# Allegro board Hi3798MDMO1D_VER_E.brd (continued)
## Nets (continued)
GND: C1.2 C2.2 C3.2 C4.2 C5.2 C7.2 C8.2 C9.2 C10.2 C11.2 C12.2 C13.2 C14.2 C15.2 C16.2 C17.2 C18.2 C19.2 C20.2 C21.2 C22.1 C23.2 C24.2 C25.2 C26.2 C27.2 C28.2 C29.2 C30.2 C31.2 C33.1 C34.2 C35.2 C36.2 C37.2 C38.2 C39.2 C40.2 C41.2 C42.1 C43.2 C44.2 C45.2 C46.2 C47.2 C48.2 C49.2 C50.2 C51.2 C52.2 C53.2 C56.2 C57.2 C58.2 C59.2 C60.2 C61.2 C62.2 C63.2 C64.2 C66.2 C67.2 C68.2 C69.2 C70.2 C71.2 C72.2 C74.2 C75.2 C78.2 C79.2 C85.2 C86.2 C87.2 C88.2 C89.2 C90.2 C91.2 C92.2 C93.2 C94.2 C95.2 C96.2 C97.2 C98.2 C99.2 C100.2 C101.2 C102.2 C103.2 C104.2 C105.2 C106.2 C107.2 C108.2 C109.2 C110.2 C111.2 C112.2 C113.2 C114.2 C115.2 C116.2 C117.2 C118.2 C119.2 C120.2 C121.2 C123.2 C124.2 C126.2 C127.2 C128.2 C129.2 C130.2 C131.2 C132.2 C133.2 C134.2 C135.2 C137.2 C138.2 C139.2 C140.2 C142.2 C143.2 C144.2 C149.2 C150.2 C151.2 C152.2 C153.2 C154.2 C158.2 C161.2 C162.2 C164.2 C167.2 C168.2 C169.2 C177.2 C180.2 C181.2 C182.2 C184.2 C185.2 C186.2 C188.2 C189.2 C190.2 C191.2 C193.2 C194.2 C195.2 C196.2 C197.2 C198.2 C199.2 C200.2 C201.2 C203.2 C204.2 C205.2 C208.2 C209.2 C211.2 C212.2 C213.2 C216.2 C218.2 C219.2 C220.2 C221.2 C225.2 C226.2 C227.2 C228.2 C232.2 C235.2 C236.2 C237.2 C238.2 C241.2 C243.2 C245.2 C248.2 C249.2 C250.1 C251.2 C255.1 C257.2 C263.2 C264.2 C270.2 C271.2 C275.2 C278.2 C279.2 C281.2 C282.2 C283.2 C284.2 C285.2 C286.2 C287.2 C288.2 C289.2 C290.2 C291.2 C292.2 C293.2 C295.2 C297.2 C298.2 C299.2 C300.2 C301.2 C302.2 C303.2 C304.2 C305.2 C306.2 C307.2 C316.2 C317.2 C320.2 C323.2 C324.2 C334.2 C336.2 C339.2 C363.2 C364.2 C365.2 C391.2 D1.2 D3.2 D6.2 D9.1 J1.2 J1.3 J2.2 J2.7 J2.9 J2.10 J2.12 J3.1 J4.2 J4.3 J5.2 J5.3 J10.2 J10.3 J12.4 J12.5 J12.6 J13.4 J13.7 J13.10 J13.11 J18.1 J21.6 J21.10 J21.11 J21.12 J21.13 J21.14 J21.15 J26.2 J26.5 J26.8 J26.11 J26.17 J26.20 J26.21 J26.22 J26.23 J34.5 LED1.2 Q1.2 Q2.2 Q4.2 Q5.2 Q8.2 R8.1 R9.2 R11.1 R13.1 R18.1 R25.1 R32.1 R38.1 R39.2 R41.1 R42.1 R43.2 R45.2 R48.2 R50.2 R51.2 R52.2 R54.1 R55.1 R56.1 R57.2 R61.1 R71.1 R75.1 R78.1 R82.2 R85.2 R87.1 R89.2 R93.2 R99.1 R100.2 R103.2 R104.2 R124.2 R130.2 R139.2 R145.2 R146.2 R149.2 R173.2 R183.2 R210.2 R229.2 S1.1 S1.3 S1.4 S2.3 S2.4 S2.5 S2.6 U1.A1 U1.A2 U1.A3 U1.A23 U1.AA2 U1.AA3 U1.AA8 U1.AA13 U1.AA14 U1.AA15 U1.AA17 U1.AA18 U1.AA20 U1.AB1 U1.AB4 U1.AB6 U1.AB10 U1.AB12 U1.AC1 U1.AC3 U1.AC5 U1.AC9 U1.AC11 U1.AC23 U1.B3 U1.B8 U1.B20 U1.B23 U1.C3 U1.C4 U1.C6 U1.C8 U1.C13 U1.C15 U1.C17 U1.C20 U1.C21 U1.C22 U1.D4 U1.D6 U1.D9 U1.D13 U1.D14 U1.D15 U1.D17 U1.D19 U1.D20 U1.D21 U1.D22 U1.E4 U1.E16 U1.E17 U1.E21 U1.E22 U1.F4 U1.F21 U1.G3 U1.G4 U1.G12 U1.G13 U1.G16 U1.G20 U1.H3 U1.H10 U1.H11 U1.H12 U1.H13 U1.H14 U1.H15 U1.H20 U1.J2 U1.J10 U1.J11 U1.J12 U1.J15 U1.J20 U1.K1 U1.K3 U1.K5 U1.K10 U1.K11 U1.K12 U1.K15 U1.K16 U1.L3 U1.L4 U1.L11 U1.L12 U1.L15 U1.L20 U1.L21 U1.M6 U1.M8 U1.M11 U1.M12 U1.M15 U1.M20 U1.N2 U1.N3 U1.N5 U1.N15 U1.N16 U1.N17 U1.P1 U1.P5 U1.P16 U1.P19 U1.P20 U1.R2 U1.R4 U1.R6 U1.R20 U1.T1 U1.T11 U1.U2 U1.U5 U1.U20 U1.V4 U1.V10 U1.V21 U1.W3 U1.W8 U1.W11 U1.W13 U1.W15 U1.W19 U1.W21 U1.Y1 U1.Y3 U1.Y7 U1.Y9 U1.Y18 U1.Y20 U1.Y23 U2.1 U2.6 U3.A1 U3.A8 U3.B1 U3.B2 U3.B8 U3.C9 U3.D1 U3.D8 U3.D9 U3.F2 U3.F8 U3.J1 U3.J9 U3.L1 U3.L9 U3.N1 U3.N9 U4.2 U5.1 U5.4 U5.10 U5.14 U6.A1 U6.A8 U6.B1 U6.B2 U6.B8 U6.C9 U6.D1 U6.D8 U6.D9 U6.F2 U6.F8 U6.J1 U6.J9 U6.L1 U6.L9 U6.N1 U6.N9 U7.1 U7.5 U10.2 U11.2 U12.2 U13.2 U14.4 U14.9 U15.2 U19.2 U19.13 U19.23 U19.25 U19.36 U19.48 U20.A1 U20.A8 U20.B1 U20.B2 U20.B8 U20.C9 U20.D1 U20.D8 U20.D9 U20.F2 U20.F8 U20.J1 U20.J9 U20.L1 U20.L9 U20.N1 U20.N9 U21.A1 U21.A8 U21.B1 U21.B2 U21.B8 U21.C9 U21.D1 U21.D8 U21.D9 U21.F2 U21.F8 U21.J1 U21.J9 U21.L1 U21.L9 U21.N1 U21.N9 U22.AA4 U22.AA6 U22.K4 U22.M7 U22.P5 U22.R10 U22.U8 U22.Y2 U22.Y5 U23.3 U23.8 U24.3 U24.8 U28.2 U28.9 X2.2 X2.4
VDD_AUDIO: C158.1 C320.1 R66.2 R91.1 R179.2 U5.9
ADAC_VOUTL: C350.2 R50.1 U1.B22
ADAC_VOUTR: C351.1 R183.1 U1.A22
AUDIO_L: C339.1 J34.3 R72.2
AUDIO_R: C140.1 J34.2 R74.1
CORE_CTRL: R23.2 U1.H22
CPU_CTRL: R21.2 U1.H23
CVBS: C79.1 C80.1 L6.1 R9.1 U1.E23
CVBS_OUT: C17.1 C80.2 D9.3 J34.4 L6.2
DDR_ADDR0: RN6.1 U1.AA12 U3.K3 U6.K3 U20.K3 U21.K3
DDR_ADDR1: RN4.2 U1.Y11 U3.L7 U6.L7 U20.L7 U21.L7
DDR_ADDR2: RN6.3 U1.W14 U3.L3 U6.L3 U20.L3 U21.L3
DDR_ADDR3: RN6.2 U1.AC14 U3.K2 U6.K2 U20.K2 U21.K2
DDR_ADDR4: RN4.3 U1.W12 U3.L8 U6.L8 U20.L8 U21.L8
DDR_ADDR5: RN6.4 U1.Y15 U3.L2 U6.L2 U20.L2 U21.L2
DDR_ADDR6: RN3.1 U1.AA10 U3.M8 U6.M8 U20.M8 U21.M8
DDR_ADDR7: RN2.2 U1.AB14 U3.M2 U6.M2 U20.M2 U21.M2
DDR_ADDR8: RN3.2 U1.AB11 U3.N8 U6.N8 U20.N8 U21.N8
DDR_ADDR9: RN2.3 U1.Y16 U3.M3 U6.M3 U20.M3 U21.M3
DDR_ADDR10: RN7.1 U1.Y8 U3.H7 U6.H7 U20.H7 U21.H7
DDR_ADDR11: RN4.4 U1.AB9 U3.M7 U6.M7 U20.M7 U21.M7
DDR_ADDR12: RN7.4 U1.Y10 U3.K7 U6.K7 U20.K7 U21.K7
DDR_ADDR13: RN2.1 U1.AA16 U3.N3 U6.N3 U20.N3 U21.N3
DDR_ADDR14: RN3.3 U1.AA11 U3.N7 U6.N7 U20.N7 U21.N7
DDR_ADDR15: RN7.2 U1.W10 U3.J7 U6.J7 U20.J7 U21.J7
DDR_BA0: RN2.4 U1.AC15 U3.J2 U6.J2 U20.J2 U21.J2
DDR_BA1: RN4.1 U1.AA9 U3.K8 U6.K8 U20.K8 U21.K8
DDR_BA2: RN3.4 U1.Y12 U3.J3 U6.J3 U20.J3 U21.J3
DDR_CASN: RN5.2 U1.Y14 U3.G3 U6.G3 U20.G3 U21.G3
DDR_CKE: R38.2 RN5.4 U1.W9 U3.G9 U6.G9 U20.G9 U21.G9
DDR_CLK1N: R37.1 RN1.4 U3.G7 U6.G7 U20.G7 U21.G7
DDR_CLK1P: R36.1 RN1.3 U3.F7 U6.F7 U20.F7 U21.F7
DDR_CSN: R33.1 U1.AC12 U3.H2 U6.H2 U20.H2 U21.H2
DDR_DM0: U1.K4 U3.B7
DDR_DM1: U1.L5 U6.B7
DDR_DM2: U1.AA1 U21.B7
DDR_DM3: U1.Y2 U20.B7
DDR_DQ0: U1.H4 U3.B3
DDR_DQ1: U1.H5 U3.C7
DDR_DQ2: U1.H1 U3.C2
DDR_DQ3: U1.J4 U3.C8
DDR_DQ4: U1.K2 U3.E3
DDR_DQ5: U1.J3 U3.E8
DDR_DQ6: U1.H2 U3.D2
DDR_DQ7: U1.J5 U3.E7
DDR_DQ8: U1.M4 U6.B3
DDR_DQ9: U1.N1 U6.C7
DDR_DQ10: U1.N4 U6.C2
DDR_DQ11: U1.P2 U6.C8
DDR_DQ12: U1.P4 U6.E3
DDR_DQ13: U1.R3 U6.E8
DDR_DQ14: U1.M5 U6.D2
DDR_DQ15: U1.P3 U6.E7
DDR_DQ16: U1.U1 U21.B3
DDR_DQ17: U1.T3 U21.C7
DDR_DQ18: U1.T2 U21.C2
DDR_DQ19: U1.U3 U21.C8
DDR_DQ20: U1.T5 U21.E3
DDR_DQ21: U1.U4 U21.E8
DDR_DQ22: U1.R5 U21.D2
DDR_DQ23: U1.T4 U21.E7
DDR_DQ24: U1.AB2 U20.B3
DDR_DQ25: U1.AA5 U20.C7
DDR_DQ26: U1.AC2 U20.C2
DDR_DQ27: U1.AB5 U20.C8
DDR_DQ28: U1.AA4 U20.E3
DDR_DQ29: U1.AC6 U20.E8
DDR_DQ30: U1.AB3 U20.D2
DDR_DQ31: U1.AA6 U20.E7
DDR_DQS0N: U1.L1 U3.D3
DDR_DQS0P: U1.L2 U3.C3
DDR_DQS1N: U1.M3 U6.D3
DDR_DQS1P: U1.M2 U6.C3
DDR_DQS2N: U1.V2 U21.D3
DDR_DQS2P: U1.V3 U21.C3
DDR_DQS3N: U1.W2 U20.D3
DDR_DQS3P: U1.W1 U20.C3
DDR_ODT: RN5.3 U1.AB15 U3.G1 U6.G1 U20.G1 U21.G1
DDR_PLL: C11.1 C264.1 C270.1 LB7.1 U1.N8 U1.T12
DDR_RASN: RN5.1 U1.AB16 U3.F3 U6.F3 U20.F3 U21.F3
DDR_RESETN: C298.1 C299.1 C300.1 C301.1 R46.1 U1.AB13 U3.N2 U6.N2 U20.N2 U21.N2
DDR_VREF_A: C49.1 C210.2 C211.1 R123.2 R124.1 U3.E1 U3.J8
DDR_VREF_B: C66.1 C202.2 C203.1 R84.2 R103.1 U6.E1 U6.J8
DDR_VREF_C: C86.1 C234.2 C235.1 R133.2 R139.1 U21.E1 U21.J8
DDR_VREF_D: C87.1 C224.2 C225.1 R129.2 R130.1 U20.E1 U20.J8
DDR_VTT: C118.1 C184.1 C190.1 C191.1 C201.1 C271.1 C292.1 C293.1 C295.1 C302.1 C303.1 C304.1 R17.2 R33.2 R78.2 RN1.5 RN1.6 RN2.5 RN2.6 RN2.7 RN2.8 RN3.5 RN3.6 RN3.7 RN3.8 RN4.5 RN4.6 RN4.7 RN4.8 RN5.5 RN5.6 RN5.7 RN5.8 RN6.5 RN6.6 RN6.7 RN6.8 RN7.5 RN7.6 RN7.7 RN7.8 U28.4
DDR_WEN: R17.1 U1.Y13 U3.H3 U6.H3 U20.H3 U21.H3
FE_1V1: C248.1 U1.G10
FE_3V3: C7.1 LB8.1 U1.E5
HDMI_TX0N: J26.9 U1.D16 U24.2 U24.9
HDMI_TX0P: J26.7 U1.C16 U24.1 U24.10
HDMI_TX1N: J26.6 U1.B15 U23.5 U23.6
HDMI_TX1P: J26.4 U1.A15 U23.4 U23.7
HDMI_TX2N: J26.3 U1.C14 U23.2 U23.9
HDMI_TX2P: J26.1 U1.B14 U23.1 U23.10
HDMI_TX_1V1: C78.1 C164.1 C251.1 C281.1 LB12.1 U1.G14 U1.G15
HDMI_TX_3V3: C15.1 C57.1 LB1.1 U1.E15
HDMI_TX_CEC: J26.13 R268.2 U1.C18 U4.3
HDMI_TX_HOTPLUG: C149.1 J26.19 R8.2 U1.B19 U4.4
HDMI_TX_SCL: J26.15 R186.1 U1.D18 U4.1
HDMI_TX_SDA: J26.16 R187.1 U1.A19 U4.6
HDMI_TXCN: J26.12 U1.B17 U24.5 U24.6
HDMI_TXCP: J26.10 U1.A17 U24.4 U24.7
IR_IN: D3.1 R140.1 U1.Y21
LED0_BASE: R26.2 R67.2 U1.B2
LED0_LINK_ACT: R30.2 R79.2 U1.B1
LED_GREEN: R3.2 R22.1 R48.1 U1.AB22
LED_RED: R31.1 R39.1 R60.2 U1.AC22
MOS_CTRL: C6.2 Q8.1 Q13.1 Q14.1 R118.1
MUTE_CTRL: R90.1 U1.C19
NF_ALE_EMMC_PWREN: U1.N20 U19.17
NF_CLE: U1.N21 U19.16
NF_CSN0_EMMC_CMD: R212.2 U1.N22 U19.9 U22.W5
NF_DQ0_EMMC_D0: R189.2 U1.R23 U19.29 U22.H3
NF_DQ1_EMMC_D1: R12.2 U1.R22 U19.30 U22.H4
NF_DQ2_EMMC_D2: R29.2 U1.R21 U19.31 U22.H5
NF_DQ3_EMMC_D3: R58.2 U1.T21 U19.32 U22.J2
NF_DQ4_EMMC_D4: R176.2 U1.T20 U19.41 U22.J3
NF_DQ5_EMMC_D5: R177.2 U1.U22 U19.42 U22.J4
NF_DQ6_EMMC_D6: R188.2 U1.U23 U19.43 U22.J5
NF_DQ7_EMMC_D7_BOOT_SEL0: R82.1 R202.2 U1.U21 U19.44 U22.J6
NF_RDY0_EMMC_RST: C115.1 R203.2 U1.M21 U19.7 U22.U5
NF_REN_EMMC_CLK: R65.1 U19.8 U22.W6
NF_WEN_EMMC_DET: R56.2 U1.P21 U19.18
NF_WP: R89.1 R215.2 U19.19
PWR_OFF/ON: R44.1 R51.1 U1.J23
RECOVERY: C42.2 R47.2 S1.2 U1.J22
RF0: C64.1 L1.2 U7.3
RF1: C50.1 L7.2 U2.7 U7.2
RFF0: C61.1 J5.1 L1.1
RFF1: C60.1 J4.1 L7.1
RX+_PHY0: R63.1 U1.D5 U8.3 U8.6
RX-_PHY0: R64.1 U1.C5 U8.4 U8.5
SDIO0_CARD_DETECT: J21.9 R155.2 U1.F1
SDIO0_CCLK_OUT: J21.5 R5.1
SDIO0_CCMD: J21.3 R153.2 U1.E2
SDIO0_CDATA0: J21.7 R152.2 U1.D3
SDIO0_CDATA1: J21.8 R151.2 U1.C2
SDIO0_CDATA2: J21.1 R156.2 U1.F2
SDIO0_CDATA3: J21.2 R154.2 U1.E1
SDIO0_CWPR: R25.2 U1.C1
SDIO0_PWREN: R76.1 R149.1 U1.F3
SDIO_3318: C22.2 R151.1 R152.1 R153.1 R154.1 R156.1 U1.G5
SPDIF_OUT_BOOT_SEL1: R83.1 U1.A20
STANDBY_PWROFF: R35.1 R73.1 R81.1 R88.1 R98.1 U1.AB23
TX+_PHY0: R59.1 U1.B4 U8.1 U8.8
TX-_PHY0: R62.1 U1.A4 U8.2 U8.7
UART0_RXD: J18.2 R136.2 U1.AA22
UART0_TXD: J18.3 R135.2 U1.AA23
USB0_DM: C119.1 D6.1 J12.2 U1.A6
USB0_DP: C113.1 D1.1 J12.3 U1.B6
USB01_1V1: C334.1 C336.1 LB31.2 U1.G11
USB01_3V3: C10.1 C182.1 LB20.2 U1.D7
USB1_DM: J2.4 U1.B7 U2.4 U7.7
USB1_DP: J2.3 U1.C7 U2.2 U7.6
USB2_DM: U1.L22
USB2_DP: U1.L23
USB3_DM: J13.2 U1.AC18
USB3_DP: J13.3 U1.AB18
USB3_RXN: J13.5 U1.AB20
USB3_RXP: J13.6 U1.AC20
USB3_TXN: C77.2 U1.AA19
USB3_TXP: C81.2 U1.Y19
USB_BOOT: C109.1 R40.1 S2.1 S2.2
VDAC_3V3: C9.1 C85.1 LB14.2 U1.E20 U1.F19 U1.G19
XIN: C364.1 R1.2 U1.W23 X2.1
XOUT: R1.1 R14.1 U1.W22
$4N774: C43.1 C71.1 R7.2 R21.1
$4N775: C76.1 R53.1 R70.1 R99.2 U11.6
$4N777: L2.1 U11.3
$4N782: C8.1 R73.2 U11.1
$4N811: C82.1 R13.2 R101.1 R110.1 U13.6
$4N812: C45.1 C72.1 R23.1 R102.2
$4N813: R102.1 R110.2
$4N814: L3.1 U13.3
$4N818: C5.1 R81.2 U13.1
$4N881: C84.1 R10.1 R52.1 U15.5
$4N882: L4.1 U15.3
$4N883: C30.1 R6.2 R35.2 U15.1
$4N953: R100.1 R105.1 U14.5
$4N955: D2.1 R95.1 U14.1
$4N956: C83.2 R104.1
$4N957: C24.1 C83.1 U14.6
$4N958: R4.2 U14.7
$4N975: C44.1 U14.8
$4N980: C65.1 R95.2
$4N983: C65.2 L5.1 U14.3
$4N998: R7.1 R70.2
$5N541: Q4.3 R118.2 R144.2
$5N549: Q4.1 R98.2
$6N188: C365.1 R14.2 X2.3
$6N1407: R173.1 U1.E6
$6N2001: R61.2 U1.Y17
$6N2177: R43.1 R85.1 U1.L19
$6N2315: R5.2 U1.E3
$6N2388: R65.2 U1.N23
$7N1408: C250.2 U1.G17
$7N1630: R40.2 U1.H21
$7N1639: R18.2 R87.2 U1.D8
$7N1763: R32.2 U1.F20
$8N1506: R45.1 U1.W16
$8N1514: R36.2 U1.AA7
$8N1515: R37.2 U1.AB7
$9N2352: C255.2 U1.T19
$10N1108: C196.1 Q8.3 R11.2 R24.1 U28.3
$11N1061: R54.2 U3.H8
$11N1180: R55.2 U6.H8
$12N1392: R71.2 U21.H8
$12N1506: R75.2 U20.H8
$13N604: C123.1 C124.1 U22.K2
$13N728: R68.1 U19.39
$13N778: R80.2 U19.38
$14N447: R15.1 U10.3
$14N448: R41.2 U10.4
$14N488: C29.1 C52.1 J12.1 LB2.1 U10.5
$14N520: R16.1 U12.3
$14N521: R42.2 U12.4
$14N524: C38.1 C75.1 J13.1 LB3.1 U12.5
$14N708: C81.1 J13.9
$14N709: C77.1 J13.8
$15N771: C47.1 C177.1 D3.3 R178.1
$15N777: C73.2 Q15.1 R77.2 R267.1
$15N781: Q5.1 R76.2
$15N783: Q5.3 R267.2
$15N941: Q2.1 R31.2
$15N943: Q1.1 R22.2
$15N992: LED1.3 Q1.3 R2.2
$15N993: LED1.1 Q2.3 R34.2
$16N996: C363.1 R66.1 R90.2 R229.1 U5.5
$16N997: C33.2 U5.6
$16N998: C32.1 U5.7
$16N999: C32.2 U5.8
$16N1080: R49.2 R57.1 R91.2
$16N1087: C351.2 R193.1
$16N1088: C55.1 R27.2 U5.2
$16N1091: C317.1 R19.1 R27.1 R193.2
$16N1106: C55.2 R19.2 R74.2 R146.1 U5.3
$16N1113: C350.1 R194.2
$16N1114: C316.1 R20.2 R28.2 R194.1
$16N1117: C54.2 R28.1 U5.13
$16N1132: C54.1 R20.1 R72.1 R145.1 U5.12
$16N1141: R49.1 U5.11
$17N163: C154.1 C297.1 T2.7
$17N165: J25.9 R67.1
$17N170: J25.11 R79.1
$17N171: J25.7 J25.8 R270.2
$17N172: R271.2 T2.15
$17N173: R269.2 T2.10
$17N175: J25.6 T2.9
$17N176: J25.3 T2.11
$17N177: C23.1 R269.1 R270.1 R271.1 R272.1
$17N178: J25.1 T2.16
$17N179: J25.2 T2.14
$17N180: J25.4 J25.5 R272.2
$17N184: C153.1 C307.1 T2.2
$17N263: R59.2 T2.1
$17N268: R63.2 T2.6
$17N269: R62.2 T2.3
$17N270: R64.2 T2.8
$19N506: D19.1 R268.1

Pads without a net: ID1 1; ID2 1; ID3 1; ID4 1; ID5 1; ID6 1; J2 1 6 8 11; J26 14; J34 6; M20 1; M21 1; M22 1; M23 1; NOREF#2 1; NOREF#5 1; NOREF#15 1; NOREF#24 1; NOREF#25 1; NOREF#26 1; RN1 1 2 7 8; RN7 3; T2 4 5 12 13; U1 A8 A9 A11 A12 AA21 AB8 AC8 B9 B11 B12 C9 C10 C11 C12 G21 J21 K20 K21 Y22; U2 3; U3 A3 A7 F1 F9 H1 H9; U6 A3 A7 F1 F9 H1 H9; U7 4 9 10; U11 5; U13 5; U19 3 4 5 6 10 11 14 15 20 21 22 26 27 28 33 35 40 45 46 47; U20 A3 A7 F1 F9 H1 H9; U21 A3 A7 F1 F9 H1 H9; U22 1 2 A4 A6 A9 A11 AA1 AA2 AA7 AA8 AA9 AA10 AA11 AA12 AA13 AA14 AE1 AE14 AG2 AG13 AH4 AH6 AH9 AH11 B2 B13 D1 D14 H1 H2 H6 H7 H8 H9 H10 H11 H12 H13 H14 J1 J7 J8 J9 J10 J11 J12 J13 J14 K1 K3 K5 K7 K8 K9 K10 K11 K12 K13 K14 L1 L2 L3 L4 L12 L13 L14 M1 M2 M3 M5 M8 M9 M10 M12 M13 M14 N1 N2 N3 N10 N12 N13 N14 P1 P2 P3 P10 P12 P13 P14 R1 R2 R3 R5 R12 R13 R14 T1 T2 T3 T5 T12 T13 T14 U1 U2 U3 U6 U7 U10 U12 U13 U14 V1 V2 V3 V12 V13 V14 W1 W2 W3 W7 W8 W9 W10 W11 W12 W13 W14 Y1 Y3 Y6 Y7 Y8 Y9 Y10 Y11 Y12 Y13 Y14; U28 5 7 8

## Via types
v1: diameter 0.508, hole 0.254, TOP to BOTTOM, 835 vias
v2: diameter 0.457, hole 0.203, TOP to BOTTOM, 547 vias

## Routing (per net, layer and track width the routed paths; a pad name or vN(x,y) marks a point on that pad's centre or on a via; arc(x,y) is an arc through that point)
1V1_CORE: length 12.3
  TOP w0.508: C82.2 R101.2 v1(70.2,10.33)
  BOTTOM w0.381: 66.67,19.15 66.18,18.66 66.18,16.31 67.38,15.11 67.38,13.5 69.18,11.69 69.18,11.35 v1(70.2,10.33)
  vias: v1(66.74,21.13) v1(66.74,20.42) v1(66.74,19.71) v1(67.12,28.32) v1(67.47,21.13) v1(67.47,20.42) v1(67.47,19.71) v1(67.88,28.7) v1(67.85,27.76) v1(68.23,21.13) v1(68.23,20.42) v1(68.23,19.71) v2(57.12,38.2) v2(57.12,37.4) v2(57.12,36.6) v2(57.92,37.4) v2(57.92,36.6) v2(58.72,37.4) v2(59.52,39.82) v2(59.52,37.4) v2(60.32,39.8) v2(60.32,39) v2(60.32,37.4) v2(62.56,33.31) v2(62.56,32.73) v2(63.14,33.31) v2(63.14,32.73) v2(63.72,33.31) v2(63.72,32.73)
1V1_CPU: length 11.4
  TOP w0.381: v2(69.88,49.7) 69.93,49.65 69.93,46.4 70.34,45.99 70.34,44.05 70.62,43.77 70.94,43.77 ; v1(69.99,52.01) 70.27,52.29 R53.2 C76.2
  BOTTOM w0.381: v1(69.99,52.01) 69.6,51.63 69.6,49.98 v2(69.88,49.7)
  vias: v1(69.76,39.39) v1(69.76,38.65) v1(70.67,39.39) v1(70.67,38.65) v1(71.61,39.39) v1(71.61,38.65) v1(72.55,39.39) v1(72.55,38.65) v2(61.92,40.6) v2(61.92,39) v2(61.92,38.2) v2(62.72,40.6) v2(62.72,39.8) v2(62.72,39) v2(62.72,38.2)
1V5_DDR3: length 99.7
  TOP w0.203: U20.G2 51.55,14.89 51.4,14.73 51.4,14.73 51.14,14.48 v2(50.39,14.48) ; v2(37.71,33.58) 37.71,32.57 U6.G2 ; v2(35.25,14.48) 36.27,14.48 U21.G2 ; v2(37.71,48.04) 37.71,47.2 U3.G2
  TOP w0.254: U6.G8 v2(37.72,26.96) ; U3.G8 v2(37.72,41.59) ; U21.G8 v2(41.88,14.49) ; U20.G8 v2(57.01,14.49) ; U21.E2 v2(37.08,16.89) ; v2(36.12,26.16) U6.K9
  TOP w0.305: U6.E2 v2(40.12,31.76) ; v2(58.06,16.44) 58.02,16.49 U20.E9 ; v2(36.68,20.26) U21.A2 ; U3.B9 v2(42.52,40.79) U3.A9 ; U6.A9 v2(42.52,26.16) U6.B9 ; v2(43.15,12.49) U21.K9 ; v2(41.34,33.6) 41.32,33.57 U6.C1 ; U3.A2 v2(43.48,46.79) ; U20.C1 50.4,18.09 v2(50.38,18.12) ; v2(35.2,12.49) 35.2,12.49 U21.K1 ; v2(40.12,47.19) U3.E2 ; U6.E9 v2(39.32,26.96) ; v2(40.92,28.56) U6.D7 ; v2(41.72,47.19) 41.32,47.59 U3.C1 ; v2(50.34,12.49) U20.K1 ; v2(36.28,18.49) U21.C1 ; v2(58.04,12.49) U20.K9 ; v2(40.92,43.19) U3.D7 ; U3.K1 v2(35.72,48.16) ; v2(52.26,20.14) U20.A2 ; U20.B9 v2(57.81,19.29) U20.A9 ; v2(43.28,10.89) U21.M9 ; v2(58.29,10.89) U20.M9 ; U20.E2 v2(52.21,16.89) ; v2(40.28,17.69) U21.D7 ; U3.M9 v2(34.12,40.11) ; U3.M1 v2(34.12,48.16) ; U6.K1 35.72,33.63 v2(35.72,33.64) ; v2(35.72,40.32) 35.72,41.19 U3.K9 ; v2(43.92,17.45) 42.95,16.49 U21.E9 ; U6.A2 v2(43.32,31.76) ; v2(50.34,10.89) U20.M1 ; v2(35.25,10.89) U21.M1 ; U21.B9 v2(42.68,19.29) U21.A9 ; U6.M9 v2(34.12,25.56) ; v2(34.12,33.58) U6.M1 ; U20.D7 v2(55.41,17.69)
  TOP w0.381: v1(37.04,5.02) 37.35,4.72 C88.1 ; v1(39.94,4.92) 40.14,4.72 C117.1 ; R10.2 C84.2 17.2,37.64 23.91,37.64 v1(26.07,39.8) ; C106.1 v2(28.53,28.32) ; C95.1 53.2,4.36 v2(53.55,4.72) ; C89.1 v1(28.94,40.43) ; U3.E9 v2(40.12,40.79)
  BOTTOM w0.305: v2(42.68,19.29) 42.68,19.29 C249.1 ; v2(57.01,14.49) 57.01,15.25 C162.1 ; C232.1 57.83,19.27 v2(57.81,19.29) ; C279.1 37.58,41.45 v2(37.72,41.59) ; v2(35.25,14.48) 35.06,14.68 C290.1
  BOTTOM w0.381: v2(40.12,47.19) 40.29,47.37 C221.1 ; R129.1 C224.1 v1(49.69,21.41) ; C144.1 55.51,17.6 v2(55.41,17.69) ; C218.1 35.72,39.57 v2(35.72,40.32) ; C129.1 41.33,33.59 v2(41.34,33.6) 42.05,34.3 R84.1 C202.1 ; v2(35.72,33.64) 35.72,33.96 35.59,34.08 C205.1 ; v2(36.28,18.49) 36.43,18.33 C289.1 36.43,17.53 v2(37.08,16.89) ; v2(58.29,10.89) 58.02,10.89 C226.1 ; C167.1 41.91,14.52 v2(41.88,14.49) ; v2(40.92,28.56) 41,28.65 C208.1 ; v2(52.26,20.14) 52.31,20.18 C287.1 ; v2(34.12,33.58) 34.12,33.88 34.07,33.93 C278.1 ; C238.1 43.93,10.89 v2(43.28,10.89) ; C126.1 34.12,25.24 v2(34.12,25.56) ; v2(39.32,26.96) 39.53,26.75 C285.1 ; v2(42.52,40.79) 42.52,40.6 C284.1 ; C151.1 50.44,18.18 v2(50.38,18.12) ; C286.1 52.29,16.96 v2(52.21,16.89) ; v2(50.34,10.89) 49.67,10.89 C228.1 ; C236.1 43.69,17.67 v2(43.92,17.45) ; C130.1 42.91,25.77 v2(42.52,26.16) ; C234.1 33.41,20.01 v1(33.13,19.73) 33,19.6 R133.1 ; C161.1 58.63,12.49 v2(58.04,12.49) ; R123.1 42.66,50.59 v1(43.14,50.11) 42.73,49.7 C210.1 ; v2(37.72,26.96) 37.75,26.93 C209.1 ; v2(50.34,12.49) 49.54,12.49 C291.1 ; v2(40.92,43.19) 40.72,43.38 C139.1 ; v2(37.71,48.04) 37.65,48.09 C133.1 ; v2(34.12,40.11) 34.12,39.39 C220.1 ; C168.1 36.99,19.94 v2(36.68,20.26) ; C204.1 40.12,31.13 v2(40.12,31.76) ; C169.1 34.55,12.49 v2(35.2,12.49) ; C288.1 43.9,12.49 v2(43.15,12.49) ; v2(36.12,26.16) 35.87,25.92 C131.1 ; C219.1 34.12,48.72 v2(34.12,48.16) ; v2(40.28,17.69) 40.22,17.75 C237.1 ; R46.2 v1(28.46,43.38) ; v2(40.12,40.79) 40.22,40.69 C213.1 ; C227.1 49.67,14.48 v2(50.39,14.48) ; v2(37.71,33.58) 37.68,33.61 37.68,34.39 C128.1 ; v2(58.06,16.44) 58.15,16.35 C152.1 ; v2(41.72,47.19) 41.72,47.19 C134.1 ; C241.1 34.47,10.89 v2(35.25,10.89) ; C216.1 35.67,48.2 v2(35.72,48.16) ; C212.1 43.47,46.78 v2(43.48,46.79)
  vias: v1(26.07,41.83) v1(26.07,40.81) v1(27.09,41.83) v1(27.09,40.81) v1(27.09,39.8) v1(43.34,38.04) v1(43.32,37.03) v1(48.17,51.23) v1(48.17,50.21) v1(49.06,50.59) v1(49.06,49.58) v2(46.19,17.8) v2(47.07,17.78) v2(52.32,31.8) v2(53.12,33.4) v2(53.12,32.6) v2(53.12,31.8) v2(53.92,39.8) v2(53.92,39) v2(53.92,34.2) v2(53.92,31.8) v2(54.06,37.71) v2(54.03,36.47) v2(56.32,34.2) v2(56.32,33.4) v2(58.72,33.4) v2(59.52,33.4)
3V3: length 51.3
  TOP w0.305: U1.V20 v2(65.12,32.6) U1.W20
  TOP w0.381: R136.1 v1(81.67,6.02) ; v1(79.89,6.02) R135.1 79.89,3.89 79.93,3.86 J18.4 ; R6.1 v1(17.43,39.29) ; v1(67.07,60.52) 71.92,60.52
  BOTTOM w0.381: C114.1 17.18,44.88 17.18,39.54 v1(17.43,39.29) ; C53.1 75.09,49.76 v1(75.27,49.58) ; R105.2 v1(67.07,60.52) ; R60.1 69.45,7.64 ; v1(66.03,11.28) 66.25,11.06 R3.1
  BOTTOM w0.508: 71.31,8.81 71.74,9.24 71.74,11.52 72.61,12.4 72.61,13.97 70.54,16.04 70.54,19.15 71.33,19.93 71.33,25.4 70.8,25.93 68.13,25.93 67.27,26.79 65.49,26.79 65.29,27 R88.2 65.29,27.96 65.59,28.27 66,28.27 66.28,28.55 66.28,31.16
  vias: v1(15.17,46.38) v1(15.17,45.61) v1(15.17,44.85) v1(15.93,46.38) v1(15.93,45.61) v1(15.93,44.85) v1(66.82,11.28) v1(67.56,11.28) v1(67.99,11.94) v1(68.29,11.28) v1(70.27,8.43) v1(70.27,7.54) v1(71.03,8.43) v1(71.03,7.54) v1(71.6,63.88) v1(71.6,62.99) v1(71.6,62.1) v1(72.48,63.88) v1(72.48,62.99) v1(72.48,62.1) v1(75.27,51.18) v1(75.27,50.29) v1(76.03,51.18) v1(76.03,50.29) v1(76.03,49.58) v1(84.62,56.56) v1(84.62,55.55) v1(84.62,54.53) v1(85.89,56.56) v1(85.89,55.55) v1(85.89,54.53)
3V3_MOS: length 55.5
  TOP w0.254: U1.D12 58.71,43.81 v2(58.71,43.79)
  TOP w0.305: R47.1 v1(69.06,75.82) ; v1(70.27,43.23) 69.5,42.46 R44.2
  TOP w0.381: J25.12 35.66,76.8 36.38,76.08 36.38,64.53 36.64,64.27 R30.1 37.09,63.79 35.85,62.55 v1(35.85,61.77) ; v1(63.1,50.52) 64.14,49.47 R83.2 ; v1(20.86,63.93) R26.1 21.24,64.7 21.62,65.09 21.62,67.99 20.99,68.63 20.99,75.25 22.55,76.8 J25.10 ; D9.2 v1(67.29,71.92) ; v1(51.49,67.04) D19.2
  BOTTOM w0.254: v1(70.39,25.29) 67.98,25.29 67.01,26.26 64.64,26.26 64.28,26.62 LB18.1 ; 69.44,43.23 69.27,43.06
  BOTTOM w0.381: v1(69.06,75.82) 69.06,73.69 v1(67.29,71.92) ; v1(20.86,63.93) 21.3,63.49 v1(21.3,60.37) ; v1(70.27,43.23) 69.44,43.23
  vias: v1(17.11,53.77) v1(17.11,53.01) v1(21.3,59.23) v1(23.28,26.72) v1(72.55,10.71) v1(72.55,9.95) v1(73.06,11.32) v1(73.82,11.32) v2(23.28,25.7) v2(24.16,26.72) v2(24.16,25.7) v2(53.12,43) v2(54.54,41.85) v2(55.13,41.85) v2(56.52,43.02) v2(58.73,43.2) v2(63.52,43) v2(63.52,42.2) v2(64.32,37.4) v2(75.91,43.94) v2(75.91,43.18) v2(76.8,43.94) v2(76.8,43.18)
3V3_MOS_FLASH: length 36.9
  TOP w0.203: U19.37 86.51,27.93 86.52,27.93 v1(86.52,28.01)
  TOP w0.229: v2(88.01,38.34) 88.01,38.34 U22.W4 U22.Y4 U22.AA3 88.51,39.89 v2(89.06,40.43)
  TOP w0.254: U22.AA5 87.51,40.43 v2(87.51,40.43) ; v2(86.97,35.94) 87.01,35.9 ; 87.01,35.9 U22.M6 ; 87.01,35.9 87.04,35.87 U22.N5 ; U22.K6 87.01,34.5 v2(86.65,34.86) 84.85,34.86 84.49,35.22 84.49,37 84.86,37.37 U22.T10 85.53,37.37 v2(85.54,37.36) 85.54,37.84 U22.U9 ; U19.34 85.01,25.23 v1(84.93,25.15) ; U19.24 v1(80.51,47.55) ; 86.51,45.33 U19.12
  TOP w0.305: U19.1 92.01,45.34 v1(92.27,45.09)
  TOP w0.381: v2(89.06,40.43) 89.06,41.22 88.65,41.63 87.94,41.63 87.51,41.2 87.51,40.98 v2(87.51,40.43) ; 86.51,45.33 86.51,43.53 v2(86.38,43.4) ; R58.1 v1(81.57,24.05) ; v1(85.95,24.15) R80.1 R68.2 ; R29.1 v1(81.57,25.07)
  BOTTOM w0.381: C142.1 86.38,42.45 86.09,42.16 84.34,42.16 R215.1 ; 79.98,50.16 79.98,48.08 v1(80.51,47.55) ; v1(92.27,45.09) 91.25,44.07 87.6,44.07
  vias: v1(77.18,50.8) v1(77.18,49.91) v1(78.2,50.8) v1(78.2,49.91)
3V3_SD:
  vias: v1(13.32,56.08) v1(13.32,55.29)
3V3_WIFI:
  vias: v1(17.31,27.48) v1(18.2,27.48)
5V0: length 13.9
  TOP w0.254: 74.29,56.67 74.24,56.62 74.24,54.27 74.07,54.1 73.12,54.1 72.61,54.61 v1(67.43,54.61)
  TOP w0.381: v1(74.58,16.33) 74.58,18.18 R144.1
  BOTTOM w0.381: R4.1 66.96,54.61 v1(67.43,54.61)
  vias: v1(73.8,14.4) v1(74.71,14.4) v1(75.47,14.4) v1(77.76,73.33) v1(77.76,71.93) v1(77.76,69.39) v1(78.19,61.06) v1(78.19,60.17) v1(78.65,73.33) v1(78.65,71.93) v1(78.65,69.39) v1(79.08,61.06) v1(79.08,60.17) v1(79.54,73.33) v1(79.54,71.93) v1(79.54,69.39) v1(79.97,61.06) v1(79.97,60.17)
5V0_MOS: length 4
  TOP w0.381: D20.2 v1(55.91,77.1) ; R15.2 v1(81.63,69.57) ; 76.41,13.79 76.06,13.79 76.01,13.84 74.38,13.84 R16.2
  vias: v1(45.75,62.28) v1(45.75,61.51) v1(47.05,62.28) v1(47.05,61.51) v1(69.15,66.16) v1(69.15,65.4) v1(76.28,18.89) v1(77.25,18.89) v1(77.25,18.16) v1(77.29,17.32) v1(77.71,13.41) v1(77.71,12.7) v1(78.02,14.05) v1(81.25,74.93) v1(82.01,74.93) v1(82.77,74.93)
5V0_MOS_HDMI: length 14
  TOP w0.254: 52.46,78.17 52.22,78.41 J26.18
  TOP w0.381: 52.46,78.17 52.46,77.81 v1(53.78,76.49) R187.2 54.53,75.73 55.15,75.1 D20.1 55.15,73.84 54.73,73.42 v1(54.01,73.42) U4.5 ; R186.2 v1(52,76.49)
  BOTTOM w0.381: v1(52,76.49) v1(53.78,76.49) ; C150.1 53.93,73.34 v1(54.01,73.42)
AVDD11_PLL012: length 0.6
  TOP w0.305: U1.P17 v2(61.92,36.6)
AVDD11_USB3:
  vias: v2(61.92,35)
AVDD33_ADAC: length 0.6
  TOP w0.305: U1.E19 v2(64.32,43.8)
AVDD33_PLL01: length 0.6
  TOP w0.305: v2(64.3,35.8) 63.92,35.42 U1.R19
AVDD33_USB2: length 0.6
  TOP w0.305: U1.K19 63.92,39.4 v2(64.32,39.8)
AVDD33_USB3: length 5.6
  TOP w0.254: 63.12,32.2 63.06,32.25 62.38,32.25 U1.W17
  TOP w0.305: 63.12,32.2 v2(63.52,31.8)
  BOTTOM w0.381: LB18.2 64.28,28.99 C18.1 63.74,29.54 63.74,31.58 v2(63.52,31.8)
GND: length 564.1
  TOP w0.089: 90.03,39.62 89.26,39.62 U22.Y2
  TOP w0.127: U1.G16 U1.E16 ; v2(58.72,46.2) 57.92,46.2 v2(57.92,46.2) ; U1.L3 51.12,38.6 ; 51.51,30.98 51.12,31.37 51.12,31.4
  TOP w0.152: U20.F8 56.39,15.69 56.01,15.31 55.56,15.31 v2(55.22,15.65)
  TOP w0.165: U1.AB6 53.52,29.99 53.93,30.4 53.93,31.01 U1.Y7
  TOP w0.203: U1.AA17 62.32,30.6 v2(62.72,31) ; U3.F8 39.32,42.4 39.32,43.01 39.51,43.19 v2(40.12,43.19) ; U20.F2 51.57,15.69 51.17,16.09 49.55,16.09 v2(49.31,15.85) ; U6.F8 39.34,27.78 39.34,28.48 v2(39.5,28.65) ; U1.AA15 60.72,30.75 60.32,31.15 v2(60.32,31.8) ; 55.12,32.2 55.52,32.6 v2(56.32,32.6) ; U21.D8 41.48,17.13 41.09,16.75 41.09,16.07 U21.F8 ; U1.W21 65.92,31.8 66.72,31.8 67.12,31.4 ; 62.59,43.81 63.53,43.81 U1.D19 ; U22.AA4 U22.Y5 U22.AA6 ; v2(58.72,32.6) 57.92,32.6 U1.W11 U1.V10 ; v2(59.52,32.6) 60.3,32.6 ; 51.12,30.6 51.51,30.98 52.13,30.98 52.33,30.78 52.33,30.4 51.92,29.99 U1.AB4 ; v2(51.52,35) 50.96,35 50.71,34.74 50.71,34.2 v2(50.72,34.2)
  TOP w0.229: v2(87.47,34.86) 87.52,34.86 U22.K4
  TOP w0.254: C316.2 v1(62.77,60.7) ; U19.48 v1(92.01,28.07) ; v2(59.74,13.29) 60.46,14.01 R75.1 ; v2(50.72,30.2) U1.AA3 51.12,30.6 ; U21.N1 v2(35.25,10.09) ; v2(49.92,30.2) U1.AA2 ; v1(75.73,10.71) 74.08,10.71 72.73,9.37 ; v1(91.39,45.09) 91.51,45.21 U19.2 ; J26.5 v1(45.72,78.31) ; v2(36.12,26.96) 36.52,26.56 U6.J9 ; 85.86,45.36 86.01,45.51 U19.13 ; U3.N9 33.32,40.06 v2(33.18,39.92) ; C339.2 v1(63.31,75.36) ; U20.N9 v2(58.26,10.09) ; 57.59,58.46 58.66,57.4 R183.2 ; v2(49.12,28.6) U1.AC1 ; U19.36 86.01,27.8 v1(85.81,28.01) ; v1(65.3,20.14) 65.3,21.64 61.84,25.1 v1(61.84,27.1) ; v2(86.75,40.46) 86.75,40.46 87.01,40.19 U22.AA6 ; J26.11 v1(48.72,78.31) ; v2(88.35,41.04) 88.35,40.56 88.35,40.55 88.35,40.48 88.01,40.15 U22.AA4 ; U21.N9 v2(43.13,10.09) ; v1(67.75,31.59) 67.56,31.4 67.12,31.4 ; v2(49.12,29.4) U1.AB1 ; J26.17 v1(51.72,78.31) ; U6.N1 v2(33.32,33.58) ; U21.F2 v2(36.28,15.29) ; v2(40.52,26) 40.52,26.56 U6.D9 ; D9.1 v1(66.33,72.94) ; J26.8 v1(47.22,78.31) ; R52.2 v1(13.5,38.37) ; U19.23 81.01,47.29 v1(81.27,47.55) ; C140.2 v1(60.59,75.36) ; U6.N9 v2(33.32,25.76) ; J26.2 v1(44.22,78.31) ; U19.25 80.51,27.85 v1(80.3,28.07) ; v2(50.39,10.09) U20.N1 ; R149.2 v1(30.84,50.56)
  TOP w0.305: 52.72,29 v2(52.72,28.14) ; U3.D8 v2(40.92,41.59) ; v2(52.32,37.4) 52.72,37 ; U20.C9 58.09,18.09 v2(58.09,18.09) ; v2(51.52,39.8) 51.12,39.4 v2(50.72,39) U1.L3 ; U21.A1 35.88,20.24 35.88,20.24 v2(35.88,20.25) ; U6.J1 36.52,32.96 v2(36.52,33.58) ; U3.B2 v2(42.52,47.19) U3.B1 ; v1(47.15,76.04) U24.8 U24.3 v1(47.15,73.06) ; 55.12,32.2 U1.W8 v2(54.72,31.8) ; v2(50.42,18.98) 50.51,18.89 U20.B1 ; U3.D1 v2(40.92,47.99) ; 59.12,44.2 59.12,45.8 v2(58.72,46.2) ; 51.12,45 51.12,45.8 v2(50.72,46.2) 51.12,46.6 v2(50.72,47) ; 51.12,45 51.12,45 51.12,45 ; 51.12,45 U1.C4 U1.D4 51.72,44 51.72,43.6 U1.E4 ; v1(45.58,73.01) v1(45.58,74.62) v1(45.58,76.08) ; v2(58.04,11.69) U20.L9 ; v2(57.92,38.2) U1.L12 ; v2(57.92,38.2) U1.M12 ; v2(57.92,38.2) U1.M11 ; v2(57.92,38.2) 57.52,38.6 U1.L11 ; U1.AB10 v2(56.32,30.2) ; v2(58.04,13.34) 57.99,13.29 U20.J9 ; U1.F21 65.04,42.12 U1.G20 64.72,41.8 v2(65.12,41.4) U1.H20 U1.J20 ; U1.Y9 v2(55.52,31) 55.12,30.6 ; v2(34.92,25.66) 34.92,26.56 U6.L9 ; U21.B8 v2(41.87,18.5) U21.C9 ; U1.V21 v2(65.12,33.4) U1.U20 ; C42.1 v1(69.06,76.83) ; U1.AC11 v2(57.92,29.4) U1.AB12 ; v2(67.52,29.4) 67.12,29 ; v2(35.25,13.29) U21.J1 ; 63.12,31.4 v2(62.72,31) 63.12,30.6 ; v2(61.92,31) U1.AA17 ; U1.K12 v2(57.92,39) 57.52,39.4 U1.K11 ; U1.W19 U1.Y20 v2(64.32,31) U1.AA20 ; v2(43.18,11.69) U21.L9 ; U1.D9 v2(55.52,43.8) ; U1.J15 v2(61.12,40.6) 60.72,41 U1.H15 U1.G16 ; R9.2 v1(69.79,70.48) C79.2 ; U1.C15 59.92,44.2 U1.D14 v2(59.52,43.8) ; U1.C15 v2(61.12,45.4) ; U1.C15 U1.D15 U1.E16 v2(61.92,43.8) U1.E17 ; U1.R2 v2(49.74,35.4) ; U1.P19 63.92,36.2 v2(64.32,36.6) U1.P20 ; v2(49.92,46.2) U1.A2 v2(49.92,47) 49.52,46.6 U1.A1 ; U1.C6 53.52,45 v2(53.92,44.6) 53.52,44.2 U1.D6 ; U6.B2 v2(42.52,32.56) ; C17.2 v1(70.61,75.06) ; U1.C17 v2(62.72,44.6) U1.D17 ; U20.D1 v2(50.39,17.29) ; U1.H12 58.32,41 v2(58.72,40.6) ; U1.Y1 48.95,31.4 v2(48.93,31.42) ; U21.D8 v2(41.88,17.69) U21.D9 ; U3.L9 34.92,41.19 v2(34.92,40.29) ; 51.12,32.2 51.12,31.4 ; 51.12,32.2 v2(50.72,32.6) ; 51.12,32.2 v2(51.52,32.6) U1.V4 ; U20.A1 51.25,19.92 v2(51.46,20.14) ; v2(50.39,11.69) U20.L1 ; R51.2 v1(68.87,39.12) ; U1.J2 v2(49.81,40.2) ; U1.AC9 v2(55.92,28.5) ; v2(58.72,32.6) 58.72,32.6 59.12,32.2 v2(59.52,32.6) ; v2(36.28,19.29) U21.B2 ; v2(43.13,13.29) U21.J9 ; U3.C9 v2(40.92,40.79) U3.D9 ; v2(35.02,17.27) 35.04,17.29 U21.D1 ; v2(65.12,35) 64.72,35.4 U1.R20 ; v2(57.92,39.8) 57.52,40.2 U1.J11 ; U6.L1 34.92,32.96 v2(34.92,33.58) ; U6.A1 v2(43.32,32.56) ; v2(41.87,19.3) U21.A8 ; U20.D8 v2(56.21,17.69) ; v2(51.52,41.4) 51.12,41 ; U3.J1 v2(36.52,48.16) ; v2(56.55,20.26) 56.61,20.2 U20.A8 U20.B8 ; v2(50.39,13.29) U20.J1 ; U20.B2 v2(51.41,19.29) ; U1.AA15 U1.AA14 v2(59.52,30.2) 59.12,30.6 ; 52.72,33.8 v2(53.12,34.2) ; v2(58.09,17.29) 58.09,17.29 U20.D9 ; U1.T1 v2(49.01,34.6) ; U6.B1 v2(42.52,33.36) ; v2(41.72,26.16) U6.C9 v2(41.72,26.96) U6.B8 U6.A8 v2(43.32,26.96) ; U3.A1 v2(43.48,47.59) ; 59.12,41.8 v2(59.52,41.4) U1.H14 ; v2(35.25,11.69) U21.L1 ; v2(60.32,31.8) U1.W15 ; U1.AB4 51.12,29 U1.AC3 v2(50.72,28.6) ; U3.L1 v2(34.92,48.16) ; U6.F2 v2(38.52,32.56) ; 59.12,41 v2(58.72,41.4) U1.G12 ; U1.L4 v2(51.52,38.2) ; U3.N1 v2(33.32,48.16) ; U1.N2 50.51,36.81 50.51,36.81 v2(50.72,36.6) U1.N3 51.12,37 ; v1(43.98,76.09) U23.8 U23.3 v1(43.98,73.06) ; U1.R4 v2(51.52,35) ; v2(50.72,34.2) U1.U2 ; U3.J9 36.52,41.19 v2(36.52,40.34) ; v2(40.52,33.58) U6.D1 ; v2(40.92,27.76) U6.D8 ; U1.V10 v2(56.32,32.6) ; 55.12,45 v2(55.52,45.4) 55.12,45.8 v2(55.52,46.2) ; U3.F2 v2(38.52,47.19) ; v2(64.32,38.2) U1.L20 ; 52.72,36.2 v2(52.32,36.6) ; 55.12,37.8 55.12,38.25 v2(55.05,38.32) ; U1.P1 v2(49.01,36.2) ; v2(43.32,41.59) U3.A8 ; U1.W11 v2(57.12,31.8) ; v2(49.01,39.4) U1.K1 ; v2(42.52,41.59) U3.B8
  TOP w0.356: U5.4 v1(60.11,68.52) ; U5.14 v1(63.66,70.47) 63.11,70.47 62.49,71.09 v1(62.49,71.8) R145.2 ; R146.2 v1(61.4,71.8) 61.4,71.09 60.78,70.47 v1(60.11,70.47) U5.1 ; U5.10 v1(63.66,67.87)
  TOP w0.381: v1(66.46,70.55) 66.71,70.3 R57.2 ; D1.2 v1(83.49,63.91) ; C119.2 v1(82.39,59.82) ; v1(65.36,7.11) 66.38,8.12 Q1.2 ; C88.2 v1(39.25,4.72) ; R183.2 59.19,57.04 v1(59.72,56.51) ; v1(73.82,12.04) 73.77,11.98 R13.1 ; v1(69.43,59.28) 69.44,59.28 69.82,59.66 U14.4 ; C317.2 v1(58.33,60.7) ; C89.2 v1(28.94,38.27) ; R8.1 v1(54.26,71.28) ; C301.2 51.9,5.15 C95.2 v2(51.24,4.36) ; v1(76.56,14.37) 76.56,14.6 Q4.2 ; C149.2 v1(54.26,70.27) ; R229.2 v1(56.27,72.05) ; C59.2 v1(74.97,55.37) ; R50.2 v1(62.9,57.4) ; 89.71,51.13 J3.1 ; J3.1 92.22,51.13 ; J3.1 90.97,52.38 ; J3.1 90.97,49.87 ; D6.2 v1(83.49,59.82) ; C113.2 v1(82.39,63.91) ; v2(84.92,42.77) 85.02,42.87 85.02,44.52 85.86,45.36 ; 67.35,81.9 S1.4 ; S1.4 68.8,83.35 ; S1.4 68.8,80.46 ; C363.2 v1(54.77,67.88) ; C33.1 v1(55.53,66.74) ; J13.4 86.4,17.77 ; v1(69.27,52.32) 69.27,51.46 C43.2 70.16,51.2 v1(70.39,50.97) 70.47,50.9 70.47,46.71 v1(70.54,46.63) ; U1.Y7 v2(54.72,31.8) ; C117.2 v1(42.17,4.72) ; C45.2 v1(73.08,15.62) ; U4.2 v1(49.28,73.42) ; J21.14 v1(14.39,48.07) ; R41.1 v1(84.3,69.57) ; v2(52.72,28.14) 52.36,27.78 v1(52.36,25.32) v1(52.36,24.56) 53.12,23.8 v2(53.25,23.8) ; C112.2 v1(75.35,66.21) ; C71.2 v1(67.43,52.32)
  TOP w0.508: J13.10 87.35,9.58 ; J13.10 87.35,5.82 ; J13.10 85.47,7.7 ; v1(13.17,57.32) 12.85,57.64 J21.6 10.92,57.64 ; J12.4 86.13,66.42 ; J12.4 87.51,65.35 ; J12.4 84.74,65.35 ; J12.4 86.13,64.29 ; v1(72.81,50.85) 72.78,50.87 U11.2 ; v1(72.81,50.85) v1(72.81,49.88) ; v1(72.81,50.85) v1(72.81,51.96) ; LED1.2 v1(65.13,5.21) 65.13,6.88 v1(65.36,7.11) ; v1(69.38,49.14) 69.38,48.15 68.89,47.67 C72.2 ; 88.84,66.47 J12.6 ; J12.6 86.88,68.42 ; J12.6 88.84,70.38 ; J12.6 90.79,68.42 ; J12.5 90.79,55.28 ; J12.5 88.84,57.24 ; J12.5 88.84,53.33 ; J12.5 86.88,55.28
  TOP w0.635: J10.2 85.35,85.38 ; J10.2 81.49,85.38 ; J10.2 83.42,86.71 ; J26.22 56.66,86.76 ; J26.22 55.47,84.93 ; J26.22 54.28,86.76 ; 79.39,83.18 J10.3 ; J10.3 80.72,85.11 ; J10.3 80.72,81.25 ; 74.55,83.21 S1.1 ; S1.1 74.55,85.6 ; S1.1 73.35,84.4 ; S1.1 75.74,84.4 ; 77.3,80.2 J1.2 ; J1.2 78.62,82.36 ; J1.2 79.94,80.2 ; J1.2 78.62,78.04 ; J26.21 42.16,80.8 ; J26.21 39.78,80.8 ; J26.21 40.97,82.88 ; J26.21 40.97,78.72 ; S1.3 77.25,81.9 ; S1.3 74.35,81.9 ; S1.3 75.8,83.35 ; S1.3 75.8,80.46 ; 65.16,76.05 J34.5 ; J34.5 66.41,77.65 ; J34.5 63.92,77.65 ; J34.5 65.16,79.25 ; 40.97,84.93 J26.23 ; J26.23 39.78,86.76 ; J26.23 42.16,86.76 ; 85.58,83.7 J1.3 83.42,82.43 ; 89.49,20.84 J13.11 87.35,18.96 ; 54.28,80.8 J26.20 ; J26.20 55.47,78.72 ; J26.20 56.66,80.8 ; J26.20 55.47,82.88
  GND02 w0.635: J13.4 85.35,18.75 ; J13.4 86.33,17.77 ; J13.4 85.35,16.79 ; 39.85,86.76 J26.23 ; J26.23 42.09,86.76 ; J26.23 40.97,85.01 ; 74.43,81.9 S1.3 ; S1.3 75.8,83.28 ; S1.3 77.17,81.9 ; S1.3 75.8,80.53 ; 74.55,83.29 S1.1 ; S1.1 75.67,84.4 ; S1.1 74.55,85.52 ; S1.1 73.43,84.4 ; J10.2 85.28,85.38 ; J10.2 83.42,86.63 ; J10.2 81.57,85.38 ; 65.13,1 LED1.2 ; LED1.2 66.25,2.12 ; LED1.2 65.13,3.24 ; LED1.2 64.02,2.12 ; J34.5 65.16,79.18 ; J34.5 66.33,77.65 ; J34.5 63.99,77.65 ; J34.5 65.16,76.13 ; 40.97,78.79 J26.21 ; J26.21 39.85,80.8 ; J26.21 40.97,82.81 ; J26.21 42.09,80.8 ; 23.08,34.4 J2.2 23.08,36.64 ; 85.51,83.7 J1.3 83.42,82.5 ; J12.4 86.13,66.34 ; J12.4 86.13,64.36 ; J12.4 84.82,65.35 ; J12.4 87.44,65.35 ; 90.97,49.94 J3.1 ; J3.1 92.15,51.13 ; J3.1 90.97,52.31 ; J3.1 89.78,51.13 ; J10.3 80.72,85.03 ; J10.3 79.46,83.18 ; J10.3 80.72,81.32 ; J1.2 79.87,80.2 ; J1.2 78.62,82.28 ; J1.2 78.62,78.12 ; J1.2 77.38,80.2 ; 17.47,7.53 J2.9 ; J2.9 17.47,9.51 ; J2.9 18.46,8.52 ; 82.87,14.27 J13.7 84.83,14.27 ; S1.4 68.8,83.28 ; S1.4 67.43,81.9 ; S1.4 68.8,80.53 ; S1.4 70.17,81.9 ; J18.1 83.68,3.17 ; J18.1 83.68,1.32 ; J18.1 84.41,2.24 ; 13.48,8.52 J2.7 ; J2.7 14.47,9.51 ; J2.7 14.47,7.53 ; D3.2 73.62,2.12 ; D3.2 71.64,2.12 ; D3.2 72.63,3.11 ; D3.2 72.63,1.13 ; J2.12 26.74,8.52 ; J2.12 25.75,9.51 ; J2.12 25.75,7.53 ; 54.35,80.8 J26.20 ; J26.20 56.59,80.8 ; J26.20 55.47,78.79 ; J26.20 55.47,82.81 ; 86.96,68.42 J12.6 ; J12.6 88.84,66.54 ; J12.6 88.84,70.3 ; J12.6 90.72,68.42 ; 85.54,7.7 J13.10 ; J13.10 89.15,7.7 ; J13.10 87.35,5.9 ; J13.10 87.35,9.5 ; J13.11 87.35,22.64 ; J13.11 85.54,20.84 ; J13.11 89.15,20.84 ; J13.11 87.35,19.04 ; J12.5 90.72,55.28 ; J12.5 88.84,57.16 ; J12.5 88.84,53.4 ; J12.5 86.96,55.28 ; 55.47,85.01 J26.22 ; J26.22 54.35,86.76 ; J26.22 56.59,86.76 ; 22.75,7.53 J2.10 ; J2.10 21.76,8.52 ; J2.10 22.75,9.51
  BOTTOM w0.127: v2(62.72,37.4) 62.39,37.73 61.67,37.73 ; 61.83,41.09 61.45,40.71 ; 67.75,41.4 67.78,41.37 ; 54.34,46.05 53.96,45.66 ; 41.13,40.84 41.88,41.59 v2(42.52,41.59) v2(43.32,41.59)
  BOTTOM w0.203: 37.73,20.26 37.52,20.06 37.52,19.22 37.12,18.82 C168.2 ; 64.74,60.83 64.99,61.09
  BOTTOM w0.254: C118.2 v1(36.13,55.16) ; C295.2 v1(33.08,55.16) ; C292.2 v1(34.6,55.16) ; C271.2 v1(37.65,55.16) ; v1(66.96,10.08) 67.42,10.54 R48.2 ; v2(65.12,41.4) 65.17,41.35 67.7,41.35 ; v1(37.47,50.16) 37.65,49.98 C133.2 ; C109.2 v1(79.26,43.43) ; C293.2 v1(31.56,55.16)
  BOTTOM w0.305: v2(41.87,19.3) 41.87,19.3 C249.2 ; 42.71,28.57 41.77,29.51 v2(41.64,29.51) 41.03,29.51 v2(40.65,29.89) ; C279.2 v2(37.58,39.61) ; R61.1 63,28.9 v2(63.43,28.47)
  BOTTOM w0.356: v2(38.05,13.69) 38.08,13.66 C86.2
  BOTTOM w0.381: v2(53.07,13.63) 53.6,13.63 C87.2 ; C221.2 40.29,49.2 v2(40.8,49.7) ; v1(85.81,28.01) 85.86,27.96 C143.2 ; C232.2 58.46,18.46 v2(58.09,18.09) ; C307.2 v1(26.48,66.15) ; C218.2 35.85,37.99 v2(35.79,37.93) ; R39.2 67.27,6.96 ; v2(34.04,37.77) 34.15,37.87 C220.2 ; v2(47.91,14.4) 48.04,14.27 C227.2 ; C285.2 v2(39.53,24.94) ; v2(66.72,43.8) 66.63,43.71 R32.1 ; C291.2 v2(47.99,12.62) ; C287.2 51.49,20.17 v2(51.46,20.14) ; C241.2 33.61,10.84 v1(32.99,10.84) ; R103.2 41.16,34.22 v2(40.52,33.58) 40.52,33.58 C129.2 ; v2(36.92,30.87) 37.22,30.57 C66.2 ; v2(36.92,45.6) 36.92,45.17 C49.2 ; v2(56.21,17.69) 56.32,17.58 C144.2 ; v2(37.37,35.89) 37.63,35.63 C128.2 ; C168.2 36.75,18.82 v2(36.28,19.29) ; C154.2 v1(32.83,66.15) ; C278.2 34.07,35.79 v2(34.04,35.83) ; v2(53.01,18.44) 53.02,18.43 C286.2 ; C153.2 v1(23.88,66.15) ; C204.2 41.7,30.98 v2(41.72,30.96) ; C208.2 40.99,27.83 v2(40.92,27.76) ; v2(58.26,10.09) 57.9,9.72 C226.2 ; C5.2 72.35,16.36 v1(73.08,15.62) ; v1(35.34,24.18) 35.85,24.68 C131.2 ; C169.2 33.61,12.39 33.59,12.37 v1(33,12.37) ; C237.2 39.48,18.94 v2(39.77,19.24) ; v2(45.62,10.68) 45.56,10.74 C238.2 ; v2(35.48,18.49) 35.62,18.35 C289.2 ; C139.2 42.1,43.84 v2(42.3,43.63) ; C167.2 43.97,14.52 v2(43.98,14.51) ; C248.2 55.46,39.9 v2(55.43,39.87) ; C216.2 35.54,49.73 35.54,50.19 v1(35.42,50.31) ; C288.2 45.53,12.29 v2(45.54,12.28) ; C228.2 47.92,11.12 v2(47.9,11.14) ; 52.76,46.02 R173.2 53.3,45.49 ; v2(37.76,24.88) 37.75,24.89 C209.2 ; v2(50.42,18.98) 50.28,18.84 R130.2 C225.2 ; R38.1 55.05,18.51 v2(54.76,18.23) ; C161.2 59.62,13.17 v2(59.74,13.29) ; v2(35.48,19.29) 35.13,19.29 C235.2 R139.2 34.73,17.56 v2(35.02,17.27) ; Q8.2 v2(43.63,49.41) ; C290.2 v1(32.9,14.68) ; v2(55.22,15.65) 55.4,15.46 C162.2 ; C108.2 v2(64.32,31) 64.7,30.62 64.7,30.3 65.44,29.56 C18.2 ; C130.2 42.1,25.78 v2(41.72,26.16) ; C219.2 v2(33.36,49.65) ; C284.2 v2(43.57,39.39) ; v2(50.39,17.29) 50.47,17.37 C151.2 ; C297.2 v1(30.11,66.15) ; 66.15,53.87 C44.2 ; v2(58.09,17.29) 58.21,17.17 C152.2 ; C236.2 41.89,17.67 v2(41.88,17.69) ; v2(41.69,36.88) 41.59,36.77 C203.2 ; C126.2 32.26,24.89 v2(32.22,24.85) ; R210.2 v1(16.83,58.11) ; v2(44.43,45.26) 44.28,45.11 C212.2 ; C263.2 v1(15.5,58.11) ; R78.1 v1(41.92,51.35) ; C323.2 86.77,40.44 86.75,40.46 v2(86.75,40.46) ; C205.2 35.59,35.76 v2(35.51,35.84) ; C53.2 74.39,51.44
  BOTTOM w0.508: v1(13.17,57.32) 13.18,57.34 C391.2
  vias: v1(10.96,80.69) v1(10.96,78.66) v1(10.96,68.5) v1(10.96,65.96) v1(10.96,63.42) v1(10.96,60.88) v1(10.96,35.99) v1(10.96,33.45) v1(10.96,30.91) v1(10.96,28.37) v1(10.96,8.17) v1(10.96,5.89) v1(11.08,13.25) v1(12.1,13.25) v1(12.23,81.96) v1(12.23,79.93) v1(12.23,77.39) v1(12.23,74.85) v1(12.23,72.31) v1(12.23,69.77) v1(12.23,67.23) v1(12.23,64.69) v1(12.23,44.88) v1(12.23,42.34) v1(12.23,39.8) v1(12.23,32.18) v1(12.23,29.64) v1(12.23,27.1) v1(12.23,24.56) v1(12.23,22.02) v1(12.23,19.48) v1(12.23,18.08) v1(12.23,8.17) v1(12.23,4.62) v1(13.37,14.52) v1(13.37,13.25) v1(13.37,11.98) v1(13.37,9.7) v1(13.5,71.04) v1(13.5,68.5) v1(13.5,65.96) v1(13.5,46.15) v1(13.5,43.61) v1(13.5,41.07) v1(13.5,30.91) v1(13.5,28.37) v1(13.5,25.83) v1(13.5,23.29) v1(13.5,20.75) v1(13.5,19.48) v1(13.5,18.08) v1(13.5,16.81) v1(13.5,6.78) v1(14,83.74) v1(14.39,49.96) v1(14.39,10.08) v1(14.51,16.43) v1(14.77,69.77) v1(14.77,67.23) v1(14.77,32.18) v1(14.77,30.91) v1(14.77,29.64) v1(14.77,28.37) v1(14.77,27.1) v1(14.77,25.83) v1(14.77,22.02) v1(14.77,19.48) v1(15.15,13.76) v1(15.15,12.75) v1(15.15,10.84) v1(15.27,15.54) v1(15.91,0.81) v1(16.04,68.5) v1(16.04,65.96) v1(16.29,13.76) v1(16.29,12.75) v1(16.29,10.84) v1(16.49,41.47) v1(16.67,49.96) v1(16.67,48.05) v1(16.68,85.37) v1(16.8,15.54) v1(17.05,61.51) v1(17.05,19.48) v1(17.18,24.18) v1(17.31,67.23) v1(17.31,22.02) v1(17.56,10.84) v1(17.75,86.49) v1(17.76,42.95) v1(17.76,41.47) v1(17.76,40.28) v1(17.81,0.81) v1(17.94,24.18) v1(17.94,14.27) v1(17.94,13.25) v1(18.32,19.48) v1(18.4,46.38) v1(18.58,65.96) v1(18.76,52.12) v1(18.7,49.96) v1(18.7,48.05) v1(18.7,11.48) v1(18.83,24.18) v1(18.83,15.54) v1(19.08,14.4) v1(19.08,9.7) v1(19.08,7.16) v1(19.08,4.62) v1(19.08,2.08) v1(19.41,46.38) v1(19.41,45.61) v1(19.41,44.85) v1(19.59,24.18) v1(19.59,19.48) v1(19.59,18.21) v1(19.59,16.94) v1(19.59,12.37) v1(19.85,61.51) v1(19.85,22.02) v1(19.97,15.54) v1(20.35,10.97) v1(20.35,8.43) v1(20.35,0.81) v1(20.48,13.25) v1(20.86,19.48) v1(20.99,54.4) v1(20.99,53.13) v1(20.99,51.99) v1(20.99,49.96) v1(20.99,48.05) v1(20.99,41.58) v1(20.99,40.43) v1(21.37,14.27) v1(21.81,22.86) v1(22.01,41.58) v1(22.01,40.43) v1(22.01,39.29) v1(22.26,61.51) v1(22.19,33.15) v1(22.19,31.88) v1(22.95,22.86) v1(22.95,20.7) v1(22.95,19.43) v1(22.95,14.86) v1(22.89,0.81) v1(23.02,51.99) v1(23.02,49.96) v1(23.28,60.5) v1(23.28,59.48) v1(23.53,54.4) v1(24.35,22.86) v1(24.35,20.7) v1(24.35,14.86) v1(24.35,12.83) v1(25.05,61.39) v1(25.43,0.81) v1(26.07,45.11) v1(26.2,51.99) v1(26.2,50.97) v1(26.7,4.62) v1(26.7,2.08) v1(27.65,45.11) v1(27.92,8.28) v1(27.97,0.81) v1(28.18,38.27) v1(28.48,41.83) v1(29.45,6.57) v1(30.51,0.81) v1(31.4,5.38) v1(33.05,0.81) v1(33.69,5.38) v1(33.82,55.16) v1(34.13,64.44) v1(35.59,2.54) v1(35.59,0.81) v1(35.98,5.38) v1(36.86,55.16) v1(37.33,62.87) v1(38.13,0.81) v1(39.4,87.55) v1(39.4,85.01) v1(39.4,82.47) v1(39.4,78.28) v1(39.4,75.74) v1(39.4,73.2) v1(39.4,70.66) v1(39.4,68.12) v1(39.4,65.58) v1(39.4,63.04) v1(40.67,2.54) v1(40.67,0.81) v1(41.94,75.74) v1(41.94,73.2) v1(41.94,70.66) v1(41.94,68.12) v1(41.94,65.58) v1(41.94,63.04) v1(42.3,79.03) v1(42.96,64.44) v1(42.96,63.04) v1(43.09,86.28) v1(43.09,83.74) v1(43.21,0.81) v1(43.98,64.44) v1(44.36,87.55) v1(44.36,85.01) v1(44.36,58.09) v1(44.33,56.31) v1(44.99,64.44) v1(45.25,57.17) v1(45.25,44.39) v1(45.5,53.13) v1(45.63,86.28) v1(45.63,83.74) v1(45.75,63.93) v1(45.75,63.17) v1(45.75,0.81) v1(46.14,56.31) v1(46.26,53.13) v1(46.26,51.89) v1(46.9,87.55) v1(46.9,85.01) v1(48.17,86.28) v1(48.17,83.74) v1(48.29,2.54) v1(48.29,0.81) v1(49.44,87.55) v1(49.44,85.01) v1(50.28,4.36) v1(50.71,86.28) v1(50.71,83.74) v1(50.83,0.81) v1(51.53,57.53) v1(51.98,87.55) v1(51.98,85.01) v1(53.25,86.28) v1(53.25,83.74) v1(53.37,2.54) v1(53.37,0.81) v1(54.77,65.34) v1(54.77,62.8) v1(55.91,0.81) v1(56.17,60.7) v1(56.1,48.9) v1(57.06,87.55) v1(57.06,85.01) v1(57.06,82.47) v1(57.12,80.14) v1(57.31,78.41) v1(57.31,65.34) v1(57.31,62.8) v1(57.82,75.74) v1(57.82,73.2) v1(58.45,0.81) v1(58.51,85.98) v1(58.77,4.32) v1(58.96,87.55) v1(60.55,64.38) v1(60.8,81.53) v1(60.99,0.81) v1(61.56,84.45) v1(61.93,75.36) v1(62.07,80.77) v1(62.09,6.65) v1(62.2,87.38) v1(62.32,85.98) v1(62.32,82.3) v1(62.96,79.12) v1(63.29,25.68) v1(63.53,0.81) v1(63.98,86.87) v1(64.48,82.55) v1(64.86,80.64) v1(65.25,83.95) v1(65.91,14.88) v1(66.33,75.36) v1(66.46,82.34) v1(66.67,14.88) v1(66.95,17.02) v1(67.39,59.28) v1(67.39,58.01) v1(67.39,56.74) v1(67.6,87.55) v1(67.6,85.01) v1(67.7,16.71) v1(67.75,15.92) v1(67.98,79.55) v1(67.98,77.01) v1(68.16,15.11) v1(68.16,14.24) v1(68.26,68.24) v1(68.26,67.53) v1(68.18,41.88) v1(68.23,13.51) v1(68.41,59.28) v1(68.41,58.01) v1(68.41,56.74) v1(68.61,0.81) v1(68.87,86.28) v1(68.93,13.39) v1(69.06,5.21) v1(69.2,32.76) v1(69.43,58.01) v1(69.43,56.74) v1(69.6,35.48) v1(69.82,62.99) v1(69.82,62.1) v1(69.82,13.39) v1(70.14,87.55) v1(70.27,28.11) v1(70.27,27.22) v1(70.58,13.39) v1(70.71,62.99) v1(70.71,62.1) v1(70.77,32.05) v1(71.15,0.81) v1(71.36,35.48) v1(71.41,86.28) v1(71.41,84.63) v1(71.41,82.09) v1(71.41,79.55) v1(71.66,27.22) v1(71.94,66.26) v1(71.99,32.76) v1(72.3,73.25) v1(72.3,71.98) v1(72.3,69.31) v1(72.3,68.04) v1(72.68,87.55) v1(73.04,25.25) v1(73.29,35.48) v1(73.57,73.25) v1(73.57,71.98) v1(73.57,69.31) v1(73.57,68.04) v1(73.57,27.61) v1(73.64,8.3) v1(73.64,7.54) v1(73.69,0.81) v1(73.95,86.28) v1(73.95,79.55) v1(74.01,66.27) v1(74.62,25.25) v1(74.84,73.25) v1(74.84,71.98) v1(74.84,69.31) v1(74.84,68.04) v1(74.96,27.61) v1(75.09,5) v1(75.22,87.55) v1(75.28,53.98) v1(75.28,53.09) v1(75.28,52.2) v1(75.73,9.95) v1(75.73,9.19) v1(75.73,8.43) v1(76.06,41.98) v1(76.03,39.04) v1(76.17,53.09) v1(76.17,20.7) v1(76.11,5) v1(76.18,32.74) v1(76.23,27.61) v1(76.23,0.81) v1(76.49,86.28) v1(76.49,79.55) v1(77.22,41.96) v1(77.2,39.01) v1(77.76,87.55) v1(77.76,85.01) v1(77.69,55.37) v1(77.87,22.58) v1(78.37,39.01) v1(78.77,3.35) v1(78.77,0.81) v1(79.03,86.28) v1(80.3,87.55) v1(80.3,35.1) v1(80.3,33.02) v1(80.3,30.48) v1(80.61,14.1) v1(81.31,0.81) v1(81.57,86.28) v1(81.5,71.63) v1(81.5,70.61) v1(82.26,54.99) v1(82.26,53.98) v1(82.84,87.55) v1(83.09,66.34) v1(83.15,54.48) v1(83.15,53.47) v1(83.91,73.03) v1(84.47,0.89) v1(84.74,7.03) v1(84.93,73.03) v1(85.02,28.01) v1(85.38,87.55) v1(85.57,53.47) v1(85.57,52.45) v1(85.63,68.88) v1(85.95,73.03) v1(85.95,25.15) v1(86.39,3.35) v1(86.39,0.81) v1(86.65,86.28) v1(86.65,83.74) v1(86.65,81.2) v1(86.65,78.66) v1(86.84,71.25) v1(87.47,51.94) v1(87.66,2.08) v1(87.85,71.25) v1(87.92,87.55) v1(87.92,85.01) v1(87.92,83.36) v1(87.92,80.82) v1(87.92,78.28) v1(88,10.46) v1(88.87,71.25) v1(88.93,0.81) v1(89.19,86.53) v1(89.44,48.69) v1(89.88,72.01) v1(90.46,85.26) v1(90.46,83.36) v1(90.71,22.02) v1(90.71,19.48) v1(90.71,16.94) v1(90.71,14.4) v1(90.71,11.86) v1(90.71,9.32) v1(90.84,0.81) v1(91.28,35.69) v1(91.28,34.67) v1(91.73,84.25) v1(91.98,58.85) v1(91.98,56.31) v1(91.98,48.69) v1(93,82.98) v1(93.25,60.12) v1(93.25,57.58) v1(93.25,55.04) v1(93.25,52.5) v1(93.25,49.96) v1(93.25,47.42) v1(93.25,44.88) v1(93.25,42.34) v1(93.25,39.8) v1(93.25,37.26) v1(93.25,34.72) v1(93.25,32.18) v1(93.25,29.64) v1(93.25,27.1) v1(93.25,22.02) v1(93.25,19.48) v1(93.25,16.94) v1(93.25,14.4) v1(93.25,11.86) v1(93.25,9.32) v1(93.25,6.78) v1(94.52,81.83) v1(94.52,80.31) v1(94.52,77.77) v1(94.52,75.23) v1(94.52,72.69) v1(94.52,70.15) v1(94.52,69.01) v1(94.52,66.47) v1(94.52,63.93) v1(94.52,61.39) v1(94.52,58.85) v1(94.52,56.31) v1(94.52,53.77) v1(94.52,51.23) v1(94.52,48.69) v1(94.52,46.15) v1(94.52,43.61) v1(94.52,41.07) v1(94.52,38.53) v1(94.52,35.99) v1(94.52,33.45) v1(94.52,30.91) v1(94.52,28.37) v1(94.52,25.83) v1(94.52,20.75) v1(94.52,18.21) v1(94.52,15.67) v1(94.52,13.13) v1(94.52,10.59) v1(94.52,8.05) v1(94.52,5.51) v1(95.07,22.81) v1(95.79,80.56) v1(95.79,79.04) v1(95.79,69.01) v1(95.79,67.74) v1(95.79,65.2) v1(95.79,62.66) v1(95.79,60.12) v1(95.79,57.58) v1(95.79,55.04) v1(95.79,52.5) v1(95.79,49.96) v1(95.79,47.42) v1(95.79,34.72) v1(95.79,32.18) v1(95.79,29.64) v1(95.79,27.1) v1(95.79,24.56) v1(95.79,22.02) v1(95.79,19.48) v1(95.79,6.78) v2(37.88,18.46) v2(38.39,19.2) v2(38.39,17.45) v2(38.85,17.88) v2(40.55,45.36) v2(41.23,44.65) v2(41.69,38.78) v2(42.2,23.67) v2(43.01,49.2) v2(43.04,48.28) v2(43.34,35.99) v2(43.34,19.1) v2(43.42,28.47) v2(44.2,27.63) v2(44.97,36.47) v2(44.92,28.42) v2(45.25,19.86) v2(45.4,39.24) v2(45.7,20.8) v2(46.49,21.51) v2(46.77,37.92) v2(47.51,22.65) v2(48.52,23.69) v2(49.44,23.03) v2(50.33,22.27) v2(50.76,27.48) v2(51.52,42.2) v2(52.32,42.2) v2(53.15,35.8) v2(53.46,40.78) v2(53.91,41.37) v2(54.25,40.78) v2(54.64,17.32) v2(54.77,19.48) v2(55.84,41.85) v2(56.04,39.06) v2(56.04,36.72) v2(56.22,38.34) v2(56.32,42.32) v2(56.4,35.46) v2(58.72,39.8) v2(58.68,35.1) v2(58.72,34.2) v2(63.28,34.76) v2(65.12,45.4) v2(65.12,44.6) v2(65.92,45.4) v2(66.1,37.97) v2(67.04,37.97) v2(68.22,37.85) v2(68.54,31.01) v2(70.21,28.85) v2(82.66,40.89) v2(85.57,36.58) v2(86.2,35.94) v2(86.33,37.34) v2(90,42.74) v2(90.14,36.58) v2(90.65,41.91) v2(90.65,40.26) v2(90.65,38.48)
VDD_AUDIO: length 17.6
  TOP w0.356: U5.9 v1(65.95,67.22)
  TOP w0.381: R66.2 v1(55.66,69.15) ; R91.1 v1(69.27,68.93)
  BOTTOM w0.381: v1(69.27,68.93) 67.65,68.93 v1(65.95,67.22) 64.01,69.15 v1(55.66,69.15)
ADAC_VOUTL: length 15.1
  TOP w0.203: 66.72,47.2 66.72,46.2 U1.B22
  TOP w0.254: 66.72,47.2 65.52,48.41 65.52,50.54 63.09,52.97 63.09,55.3 61.35,57.04 R50.1 61.31,57.44 C350.2
ADAC_VOUTR: length 14.6
  TOP w0.254: C351.1 60.17,57.94 60,57.78 R183.1 60,57.37 62.58,54.8 62.58,52.84 65.13,50.29 65.13,47.9 66.32,46.71 U1.A22
AUDIO_L: length 12.7
  TOP w0.254: R72.2 C339.1 62.49,75.91 61.31,77.09 59.78,77.09 59.02,77.85 59.02,81.71 J34.3
AUDIO_R: length 16.1
  TOP w0.254: J34.2 58.01,83.7 58.01,77.34 59.15,76.2 60.79,76.2 61.4,75.59 C140.1 R74.1
CORE_CTRL: length 4.7
  TOP w0.127: U1.H22 66.71,40.61 66.71,40.61 67.42,40.61 67.7,40.89 67.7,42.29 R23.2
CPU_CTRL: length 8.7
  TOP w0.127: 67.12,41 67.12,42.22 67.95,43.05 67.95,44.88 68.16,45.08 68.16,48.26 68.64,48.74 R21.2
CVBS: length 35.9
  TOP w0.254: C80.1 70.59,73.27 L6.1 70.61,72.25 C79.1 R9.1 70.61,65.66 68.74,63.8 66.56,63.8 63.59,60.83 63.59,53.1 65.9,50.8 65.9,48.84 67.55,47.19 67.55,45.51 67.29,45.26 67.29,43.57 67.12,43.4
CVBS_OUT: length 16.9
  TOP w0.254: D9.3 67.34,79.44 66.77,80.01 61.52,80.01 J34.4
  TOP w0.305: L6.2 69.79,72.28 C80.2 C17.1 69.71,74.21 D9.3
DDR_ADDR0: length 128.5
  TOP w0.127: v2(31.52,43.09) 31.52,43.54 32.24,44.26 32.95,44.26 32.97,44.28 34.51,44.28 35.72,45.48 U3.K3 ; U1.AA12 58.71,30.21 58.71,29.46 59.17,29 59.17,28.34 60.11,27.4 60.11,24.52 62.92,21.7 62.92,12.11 56.96,6.14 56.52,6.14 55.23,7.44 55.23,7.98 v2(54.86,8.35) 54.34,8.86 54.34,11.37 53.22,12.49 U20.K3 ; v2(31.29,27.44) 31.34,27.49 31.34,28.66 32.33,29.65 34.61,29.65 35.72,30.75 U6.K3 ; v2(39.84,8.32) 39.36,8.81 39.36,11.43 38.3,12.49 U21.K3
  BOTTOM w0.127: RN6.1 29.92,47.68 30.87,46.73 30.87,46.55 32.01,45.42 32.01,43.57 31.99,43.56 31.98,43.56 v2(31.52,43.09) 31.52,42.02 30.54,41.04 30.54,32.38 31.96,30.96 31.96,28.11 v2(31.29,27.44) 30.77,27.44 26.2,22.86 26.2,13.14 31.75,7.59 37.35,7.59 38.45,8.69 39.47,8.69 v2(39.84,8.32) 41.31,8.32 41.89,7.74 47.58,7.74 47.91,7.41 51.36,7.41 52.73,8.78 54.43,8.78 v2(54.86,8.35)
DDR_ADDR1: length 101.9
  TOP w0.127: v2(35.32,27.76) U6.L7 ; v2(56.21,12.09) U20.L7 ; v2(35.32,42.39) U3.L7 ; v2(41.08,12.09) U21.L7 ; U1.Y11 v2(57.12,31)
  BOTTOM w0.127: v2(57.12,31) 57.12,23.04 60.21,19.95 60.21,12.5 59.8,12.08 57.75,12.08 57.35,12.48 56.76,12.48 56.37,12.09 v2(56.21,12.09) 56.02,12.09 55.63,11.7 51.82,11.7 50.61,10.49 47.71,10.49 46.91,11.28 42.93,11.28 42.13,12.09 v2(41.08,12.09) 40.91,12.09 40.51,11.69 36.67,11.69 35.47,10.49 34.96,10.49 34.8,10.33 32.78,10.33 28.86,14.25 28.86,21.62 31.68,24.43 34.05,24.43 34.51,24.89 34.51,26.01 34.92,26.43 34.92,27.12 35.32,27.52 v2(35.32,27.76) 35.32,27.99 34.93,28.38 34.93,32.92 34.52,33.32 34.52,36.42 33.61,37.33 33.61,40.28 33.84,40.51 34.07,40.51 35.32,41.76 v2(35.32,42.39) 35.32,42.61 34.93,43 34.93,45.98 32.5,48.41 32.5,50.47 32.62,50.59 RN4.2
DDR_ADDR2: length 126.2
  TOP w0.127: U20.L3 53.03,11.69 53.79,10.94 53.79,8.14 54.3,7.62 v2(54.3,7.09) ; U3.L3 34.92,45.6 34.13,44.81 32.01,44.81 31.99,44.8 31.4,44.8 31.04,44.44 v2(31.04,43.85) ; v2(31.11,29.42) 31.9,30.21 34.21,30.21 34.92,30.92 U6.L3 ; U21.L3 38,11.69 38.72,10.97 38.72,8.07 39.38,7.41 v2(40.93,7.41) ; U1.W14 v2(59.52,31.8)
  BOTTOM w0.127: v2(59.52,31.8) 60.36,30.96 60.36,28.16 60.12,27.91 60.12,24.23 62.91,21.43 62.91,11.42 58.92,7.44 55.66,7.44 55.31,7.09 v2(54.3,7.09) 53.43,7.09 52.51,6.17 46.62,6.17 45.75,7.03 41.31,7.03 v2(40.93,7.41) 38.39,7.41 37.8,6.83 31.43,6.83 25.43,12.82 25.43,23.23 31.11,28.91 v2(31.11,29.42) 31.11,30.24 29.78,31.57 29.78,41.42 30.67,42.31 30.67,43.56 30.96,43.85 v2(31.04,43.85) 31.04,45.42 30.29,46.17 30.29,46.38 30,46.67 RN6.3
